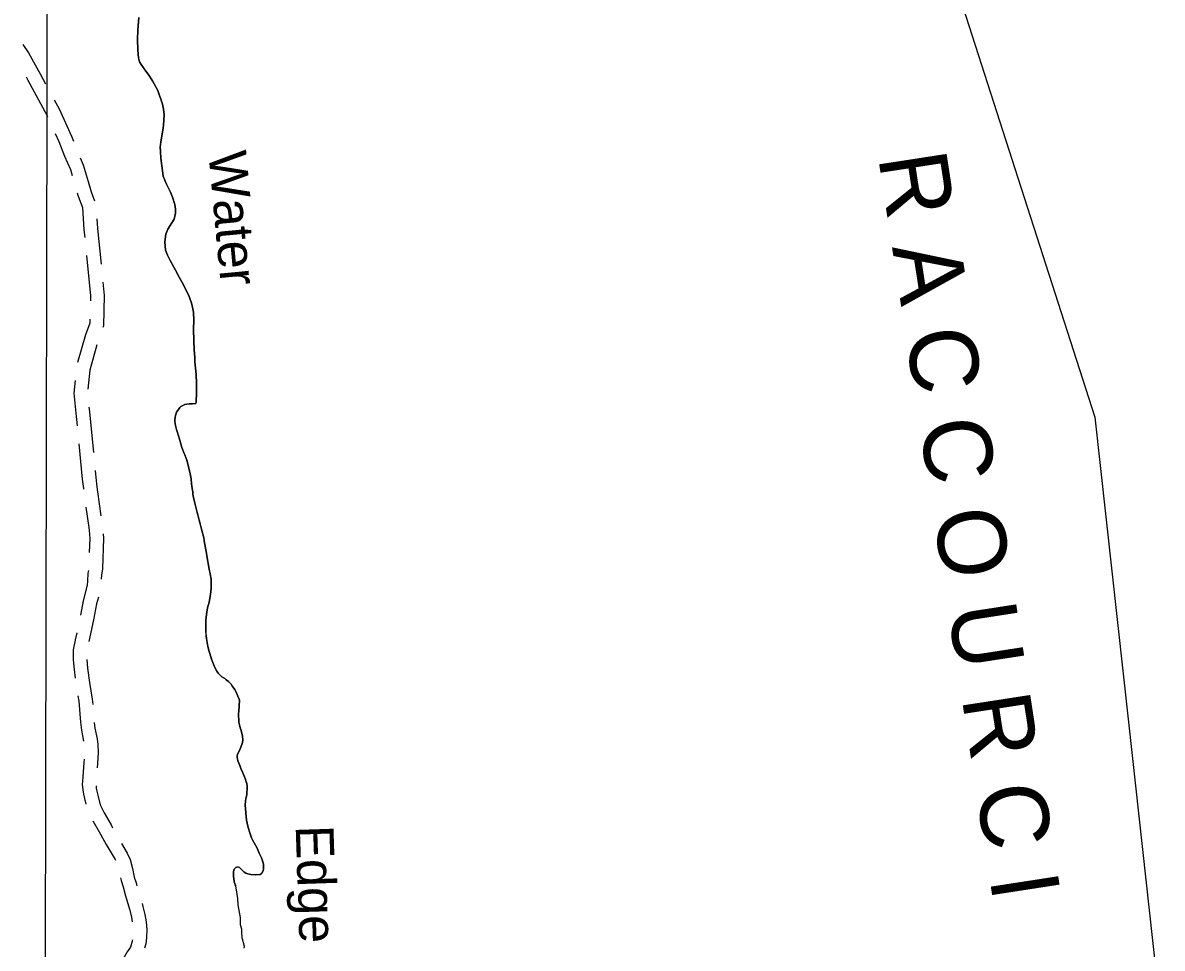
# Model space of a CAD drawing. Extents: x 3192952 to 3230831, y 849296 to 874698.
# Drawn here: x 3207569 to 3210074, y 861699 to 863734 of the extents above; entities that cross this region are included whole.
import ezdxf

# ---------------------------------------------------------------- set-up
doc = ezdxf.new("R2010")
doc.units = 0
for name, color, linetype in [('V-GRID-MAJR', 7, 'Continuous'), ('V-RIVR-IDEN', 7, 'Continuous'), ('V-ROAD-CNTR', 7, 'Continuous'), ('V-SITE-VEGE', 7, 'Continuous'), ('V-TOPO-BNDY', 7, 'Continuous'), ('V-TOPO-SHOR', 7, 'Continuous')]:
    doc.layers.add(name, color=color, linetype=linetype)

msp = doc.modelspace()

# ---------------------------------------------------------------- linework, layer by layer
at = {"layer": 'V-GRID-MAJR'}
msp.add_spline([(3207605.4, 854713.5), (3207617.8, 860773), (3207630.1, 866835.5), (3207642.5, 872898.1), (3207642.5, 872901.1)], degree=3, dxfattribs=at)
at = {"layer": 'V-ROAD-CNTR'}
msp.add_line((3207687.9, 862392.2), (3207684.5, 862376.8), dxfattribs=at)
for points in [[(3207569.5, 863686), (3207582.2, 863667.8), (3207607.3, 863621.8), (3207619.4, 863599.5)], [(3207576.8, 863615.1), (3207580.9, 863607.5), (3207622.3, 863530.8), (3207624.1, 863527)], [(3207638.3, 863564.3), (3207649.2, 863544.2), (3207676.5, 863484.7), (3207680.8, 863473.8)], [(3207640.8, 863490.6), (3207648.9, 863473), (3207661.5, 863440.7), (3207674, 863411.5), (3207678, 863397.9)], [(3207695.8, 863436.7), (3207702.2, 863421.7), (3207713.2, 863385.1), (3207719.5, 863361.9), (3207727.2, 863341.9)], [(3207689.1, 863359.5), (3207690.9, 863352.6), (3207700.5, 863327.7), (3207703.9, 863278.6), (3207705.6, 863261.7)], [(3207732.3, 863302.5), (3207733.8, 863281.1), (3207741.5, 863203)], [(3207709.5, 863221.9), (3207718.2, 863133.2), (3207718, 863122.3)], [(3207745.4, 863163.1), (3207748.3, 863134.3), (3207746.7, 863067.1), (3207745.3, 863063.6)], [(3207717.1, 863082.3), (3207716.9, 863073.1), (3207707, 863047.9), (3207690, 862986.5)], [(3207732, 863025.9), (3207716.6, 862969.9), (3207712.6, 862928.2)], [(3207684.3, 862947), (3207681.7, 862919.5), (3207686.1, 862875.3), (3207688.8, 862847.6)], [(3207714.9, 862888.4), (3207715.9, 862878.3), (3207724.7, 862789)], [(3207692.7, 862807.8), (3207700.3, 862730.7), (3207702.6, 862709.9), (3207702.8, 862708.3)], [(3207728.7, 862749.1), (3207730.2, 862733.8), (3207732.4, 862713.5), (3207733.9, 862702.2), (3207741.1, 862649.9)], [(3207708.2, 862668.7), (3207714.3, 862624.4), (3207715.4, 862617.5), (3207716.8, 862599.9), (3207715.7, 862569.3)], [(3207746, 862610.3), (3207746.8, 862600.6), (3207744.5, 862533.5), (3207744.1, 862528.1), (3207742.2, 862519.9), (3207742, 862510.6)], [(3207713.6, 862529.4), (3207712.3, 862523.7), (3207711.8, 862506.3), (3207711.3, 862497.1), (3207702.4, 862462.8), (3207696.3, 862431.3)], [(3207735.6, 862471.3), (3207731.7, 862456.1), (3207724.9, 862421.4), (3207714.5, 862373.6)], [(3207684.5, 862376.7), (3207680, 862355.5), (3207680.3, 862332.9), (3207682.2, 862311.7), (3207684.5, 862293.2)], [(3207710.3, 862334.1), (3207712, 862314.9), (3207715.9, 862283.4), (3207722.2, 862246.4), (3207723.2, 862235)], [(3207690.6, 862253.7), (3207692.5, 862242.6), (3207696.3, 862196.2), (3207698.3, 862178.5), (3207703, 862154.6)], [(3207726.6, 862195.2), (3207727.9, 862183.1), (3207732.7, 862159.4), (3207734.3, 862147), (3207735.5, 862129.2), (3207733.9, 862105), (3207733.2, 862096)], [(3207704.5, 862114.8), (3207704, 862107.2), (3207700.8, 862065.8), (3207700.1, 862060), (3207701.3, 862047.2), (3207702.8, 862037.6), (3207705.4, 862028.6), (3207708.2, 862015.8)], [(3207730.6, 862056.1), (3207731, 862051), (3207732.2, 862044.1), (3207734.5, 862035.9), (3207739.3, 862014.3), (3207748.1, 861996.9), (3207763.6, 861970.2), (3207766.9, 861964.2)], [(3207723.7, 861979.2), (3207737.5, 861955.4), (3207753.1, 861927), (3207772.4, 861894.3), (3207773.2, 861892.4)], [(3207786.5, 861929.4), (3207799.1, 861908.1), (3207805.3, 861894.1), (3207810.7, 861874.1), (3207814.5, 861855.6), (3207818.7, 861843), (3207820.5, 861836.2)], [(3207784.2, 861854.1), (3207785.5, 861847.8), (3207789.9, 861834.3), (3207795.4, 861814.5), (3207804.7, 861783), (3207808.4, 861767.5), (3207809.9, 861757.5)], [(3207831.7, 861797.7), (3207833.7, 861790.7), (3207837.9, 861773.2), (3207840.3, 861757.3), (3207842.1, 861740), (3207841.2, 861722.7), (3207839.7, 861708.5), (3207836.8, 861699.3)], [(3207810.5, 861717.7), (3207810.2, 861714.7), (3207806, 861701.3), (3207802.9, 861696.3), (3207798.7, 861691.4), (3207793, 861681.3), (3207783.7, 861666.5), (3207776.7, 861656.7), (3207766.4, 861629.7), (3207766.1, 861629.2)]]:
    msp.add_lwpolyline(points, dxfattribs=at)
at = {"layer": 'V-SITE-VEGE'}
for p, q in [((3207822.8, 863726.7), (3207824.7, 863745.5)), ((3207821.8, 863697.9), (3207822.3, 863716.7)), ((3207822.3, 863716.7), (3207822.8, 863726.7)), ((3207822, 863673.8), (3207821.8, 863697.9)), ((3207823.5, 863656.4), (3207822, 863673.8)), ((3207826.3, 863647.7), (3207823.5, 863656.4)), ((3207829.7, 863641.7), (3207826.3, 863647.7)), ((3207839.9, 863627), (3207829.7, 863641.7)), ((3207845.3, 863620.4), (3207839.9, 863627)), ((3207854.8, 863606.4), (3207845.3, 863620.4)), ((3207866.4, 863585.1), (3207854.8, 863606.4)), ((3207876.8, 863555), (3207866.4, 863585.1)), ((3207878.9, 863543.7), (3207876.8, 863555)), ((3207880.4, 863531.6), (3207878.9, 863543.7)), ((3207878, 863502.8), (3207878.6, 863508.8)), ((3207878.6, 863508.8), (3207880.4, 863531.6)), ((3207872.9, 863471.9), (3207874.8, 863484.7)), ((3207874.8, 863484.7), (3207878, 863502.8)), ((3207871.7, 863460.5), (3207872.9, 863471.9)), ((3207872.5, 863450.5), (3207871.7, 863460.5)), ((3207872.6, 863435.7), (3207872.5, 863450.5)), ((3207876.2, 863408.3), (3207872.6, 863435.7)), ((3207878.3, 863396.2), (3207876.2, 863408.3)), ((3207885.2, 863378.9), (3207878.3, 863396.2)), ((3207894.1, 863361.6), (3207885.2, 863378.9)), ((3207898.9, 863350.2), (3207894.1, 863361.6)), ((3207903.7, 863334.2), (3207898.9, 863350.2)), ((3207905.2, 863324.1), (3207903.7, 863334.2)), ((3207902.1, 863302), (3207905.3, 863314.8)), ((3207905.3, 863314.8), (3207905.2, 863324.1)), ((3207888.2, 863279.8), (3207897.4, 863293.9)), ((3207897.4, 863293.9), (3207902.1, 863302)), ((3207881.8, 863252.2), (3207883.6, 863269)), ((3207883.6, 863269), (3207888.2, 863279.8)), ((3207883.3, 863234.1), (3207881.8, 863252.2)), ((3207887.4, 863222.8), (3207883.3, 863234.1)), ((3207893.6, 863210.8), (3207887.4, 863222.8)), ((3207905.2, 863190.1), (3207893.6, 863210.8)), ((3207913.4, 863174.8), (3207905.2, 863190.1)), ((3207922.9, 863157.5), (3207913.4, 863174.8)), ((3207935.2, 863132.1), (3207922.9, 863157.5)), ((3207941.4, 863114.8), (3207935.2, 863132.1)), ((3207944.9, 863097.4), (3207941.4, 863114.8)), ((3207945.1, 863079.3), (3207944.9, 863097.4)), ((3207944.6, 863061.2), (3207945.1, 863079.3)), ((3207945.6, 863033.7), (3207944.6, 863061.2)), ((3207946.4, 863015.7), (3207945.6, 863033.7)), ((3207947.9, 862996.9), (3207946.4, 863015.7)), ((3207948, 862988.2), (3207947.9, 862996.9)), ((3207950.3, 862960.1), (3207948, 862988.2)), ((3207951.2, 862940.7), (3207950.3, 862960.1)), ((3207951.4, 862920.6), (3207951.2, 862940.7)), ((3207950.3, 862899.5), (3207951.4, 862920.6)), ((3207907.4, 862877.7), (3207911.4, 862883.8)), ((3207911.4, 862883.8), (3207914.8, 862887.8)), ((3207914.8, 862887.8), (3207917.2, 862889.8)), ((3207917.2, 862889.8), (3207921.4, 862892.5)), ((3207921.4, 862892.5), (3207926, 862894.3)), ((3207926, 862894.3), (3207930.4, 862895.5)), ((3207930.4, 862895.5), (3207934.9, 862895.8)), ((3207934.9, 862895.8), (3207942.7, 862896)), ((3207942.7, 862896), (3207950.1, 862896.7)), ((3207950.1, 862896.7), (3207950.3, 862899.5)), ((3207903.5, 862860.6), (3207904.1, 862866.2)), ((3207903.5, 862857), (3207903.5, 862860.6)), ((3207904.8, 862848.5), (3207903.5, 862857)), ((3207904.1, 862866.2), (3207904.9, 862870)), ((3207904.9, 862870), (3207907.4, 862877.7)), ((3207907.3, 862839.3), (3207904.8, 862848.5)), ((3207908.9, 862834.9), (3207907.3, 862839.3)), ((3207911, 862828.1), (3207908.9, 862834.9)), ((3207914.4, 862816.2), (3207911, 862828.1)), ((3207919.4, 862800.2), (3207914.4, 862816.2)), ((3207924.3, 862786.6), (3207919.4, 862800.2)), ((3207925.7, 862783.8), (3207924.3, 862786.6)), ((3207929.8, 862771.9), (3207925.7, 862783.8)), ((3207933.7, 862758.5), (3207929.8, 862771.9)), ((3207935.3, 862750.9), (3207933.7, 862758.5)), ((3207936.6, 862745.6), (3207935.3, 862750.9)), ((3207939.3, 862731.4), (3207936.6, 862745.6)), ((3207940.6, 862719.9), (3207939.3, 862731.4)), ((3207941.6, 862709.9), (3207940.6, 862719.9)), ((3207942.9, 862702.5), (3207941.6, 862709.9)), ((3207943.3, 862697.3), (3207942.9, 862702.5)), ((3207944.6, 862690.2), (3207943.3, 862697.3)), ((3207947.4, 862677.8), (3207944.6, 862690.2)), ((3207953, 862656.9), (3207947.4, 862677.8)), ((3207954, 862652.1), (3207953, 862656.9)), ((3207956.9, 862640.3), (3207954, 862652.1)), ((3207959.2, 862632.4), (3207956.9, 862640.3)), ((3207959.8, 862629.4), (3207959.2, 862632.4)), ((3207962.5, 862620.6), (3207959.8, 862629.4)), ((3207967.4, 862601.5), (3207962.5, 862620.6)), ((3207968.5, 862595.7), (3207967.4, 862601.5)), ((3207969.1, 862590.3), (3207968.5, 862595.7)), ((3207973, 862567.8), (3207969.1, 862590.3)), ((3207973.7, 862562), (3207973, 862567.8)), ((3207979.1, 862532.3), (3207973.7, 862562)), ((3207981.2, 862522.4), (3207979.1, 862532.3)), ((3207983.2, 862510.2), (3207981.2, 862522.4)), ((3207983.5, 862502), (3207983.2, 862510.2)), ((3207982, 862477), (3207983.4, 862490.7)), ((3207983.4, 862490.7), (3207983.5, 862502)), ((3207975.4, 862447.2), (3207978.9, 862459.9)), ((3207978.9, 862459.9), (3207982, 862477)), ((3207972.1, 862421.3), (3207974, 862438)), ((3207974, 862438), (3207975.4, 862447.2)), ((3207971.6, 862413.9), (3207972.1, 862421.3)), ((3207971.7, 862398.2), (3207971.6, 862413.9)), ((3207972.3, 862386.9), (3207971.7, 862398.2)), ((3207973.2, 862380.3), (3207972.3, 862386.9)), ((3207976.5, 862362.8), (3207973.2, 862380.3)), ((3207979.2, 862351.6), (3207976.5, 862362.8)), ((3207980.6, 862346.8), (3207979.2, 862351.6)), ((3207984.5, 862334.8), (3207980.6, 862346.8)), ((3207990.2, 862319.9), (3207984.5, 862334.8)), ((3207992.3, 862314.9), (3207990.2, 862319.9)), ((3207995.7, 862308.3), (3207992.3, 862314.9)), ((3207999, 862303.9), (3207995.7, 862308.3)), ((3208003.2, 862299.5), (3207999, 862303.9)), ((3208007.3, 862296.1), (3208003.2, 862299.5)), ((3208013.7, 862291.9), (3208007.3, 862296.1)), ((3208016.6, 862289.3), (3208013.7, 862291.9)), ((3208021.6, 862285.5), (3208016.6, 862289.3)), ((3208027.3, 862279.5), (3208021.6, 862285.5)), ((3208030.7, 862274.9), (3208027.3, 862279.5)), ((3208035.4, 862267.7), (3208030.7, 862274.9)), ((3208037.2, 862264.7), (3208035.4, 862267.7)), ((3208040.9, 862257.1), (3208037.2, 862264.7)), ((3208045.8, 862244.5), (3208040.9, 862257.1)), ((3208044.7, 862219.3), (3208045.8, 862244.5)), ((3208043.6, 862210.2), (3208043.9, 862215.1)), ((3208044, 862201), (3208043.6, 862210.2)), ((3208043.9, 862215.1), (3208044.7, 862219.3)), ((3208044.5, 862196.4), (3208044, 862201)), ((3208045.7, 862190.2), (3208044.5, 862196.4)), ((3208047.4, 862183.5), (3208045.7, 862190.2)), ((3208048.6, 862180.1), (3208047.4, 862183.5)), ((3208050, 862174.9), (3208048.6, 862180.1)), ((3208052.1, 862165.7), (3208050, 862174.9)), ((3208053.1, 862156.6), (3208052.1, 862165.7)), ((3208052.4, 862151.8), (3208053.1, 862156.6)), ((3208041.3, 862125.4), (3208047, 862137.7)), ((3208047, 862137.7), (3208051, 862147.2)), ((3208051, 862147.2), (3208052.4, 862151.8)), ((3208040.9, 862122.4), (3208041.3, 862125.4)), ((3208040.9, 862118.2), (3208040.9, 862122.4)), ((3208041.3, 862115.2), (3208040.9, 862118.2)), ((3208042.2, 862111.3), (3208041.3, 862115.2)), ((3208046.3, 862100.7), (3208042.2, 862111.3)), ((3208048.9, 862094.5), (3208046.3, 862100.7)), ((3208053.2, 862084.9), (3208048.9, 862094.5)), ((3208058.3, 862072.1), (3208053.2, 862084.9)), ((3208060.7, 862065.2), (3208058.3, 862072.1)), ((3208061.6, 862061), (3208060.7, 862065.2)), ((3208062.6, 862055.6), (3208061.6, 862061)), ((3208062.7, 862048.4), (3208062.6, 862055.6)), ((3208059.6, 862028.1), (3208061.7, 862036.1)), ((3208061.7, 862036.1), (3208062.3, 862042.1)), ((3208062.3, 862042.1), (3208062.7, 862048.4)), ((3208058.6, 862013.8), (3208059, 862022.2)), ((3208061.3, 861980.6), (3208058.6, 862013.8)), ((3208059, 862022.2), (3208059.6, 862028.1)), ((3208062.5, 861974.4), (3208061.3, 861980.6)), ((3208064.8, 861964.6), (3208062.5, 861974.4)), ((3208068.5, 861953.1), (3208064.8, 861964.6)), ((3208072.4, 861941.7), (3208068.5, 861953.1)), ((3208074.4, 861937.3), (3208072.4, 861941.7)), ((3208077.8, 861930.9), (3208074.4, 861937.3)), ((3208084.3, 861919.1), (3208077.8, 861930.9)), ((3208089.2, 861908.3), (3208084.3, 861919.1)), ((3208092.3, 861902), (3208089.2, 861908.3)), ((3208094.1, 861897.8), (3208092.3, 861902)), ((3208096.6, 861891), (3208094.1, 861897.8)), ((3208097.8, 861886.8), (3208096.6, 861891)), ((3208098.6, 861883), (3208097.8, 861886.8)), ((3208098.7, 861879), (3208098.6, 861883)), ((3208032.6, 861862.9), (3208032.8, 861867.9)), ((3208032.7, 861856.9), (3208032.6, 861862.9)), ((3208033.3, 861852), (3208032.7, 861856.9)), ((3208032.8, 861867.9), (3208034.4, 861872.8)), ((3208034.4, 861872.8), (3208037.4, 861876.6)), ((3208037.4, 861876.6), (3208042, 861878.2)), ((3208042, 861878.2), (3208045.6, 861876.6)), ((3208045.6, 861876.6), (3208049.1, 861873.8)), ((3208049.1, 861873.8), (3208055.7, 861866.9)), ((3208055.7, 861866.9), (3208060, 861864.5)), ((3208060, 861864.5), (3208063.8, 861862.9)), ((3208063.8, 861862.9), (3208066.8, 861861.9)), ((3208066.8, 861861.9), (3208071, 861860.9)), ((3208071, 861860.9), (3208081.5, 861860.4)), ((3208081.5, 861860.4), (3208091.3, 861861)), ((3208091.3, 861861), (3208094.7, 861864.3)), ((3208094.7, 861864.3), (3208097.5, 861869.5)), ((3208097.5, 861869.5), (3208098.5, 861873.7)), ((3208098.5, 861873.7), (3208098.7, 861879)), ((3208034.4, 861844.8), (3208033.3, 861852)), ((3208035.4, 861841.4), (3208034.4, 861844.8)), ((3208036.6, 861838.6), (3208035.4, 861841.4)), ((3208038.1, 861836.6), (3208036.6, 861838.6)), ((3208041.9, 861808.8), (3208038.1, 861836.6)), ((3208043.2, 861794.2), (3208041.9, 861808.8)), ((3208045.7, 861778.4), (3208043.2, 861794.2)), ((3208048.3, 861766.5), (3208045.7, 861778.4)), ((3208048.2, 861750.6), (3208048.3, 861766.5)), ((3208050.8, 861741.3), (3208048.2, 861750.6)), ((3208050.7, 861730.8), (3208050.8, 861741.3)), ((3208052, 861726.8), (3208050.7, 861730.8)), ((3208052, 861721.5), (3208052, 861726.8)), ((3208053.3, 861717.5), (3208052, 861721.5)), ((3208054.5, 861710.9), (3208053.3, 861717.5)), ((3208057.1, 861703), (3208054.5, 861710.9)), ((3208055.8, 861699), (3208057.1, 861703))]:
    msp.add_line(p, q, dxfattribs=at)
at = {"layer": 'V-TOPO-BNDY'}
for p, q in [((3209621.7, 863811.9), (3209926, 862866.7)), ((3209926, 862866.7), (3209999.7, 862195.8)), ((3209999.7, 862195.8), (3210074.1, 861524.8))]:
    msp.add_line(p, q, dxfattribs=at)
at = {"layer": 'V-TOPO-SHOR'}
for points in [[(3207824.7, 863745.5), (3207822.8, 863726.7), (3207822.3, 863716.7), (3207821.8, 863697.9), (3207822, 863673.8), (3207823.5, 863656.4), (3207826.3, 863647.7), (3207829.7, 863641.7), (3207839.9, 863627), (3207845.3, 863620.4), (3207854.8, 863606.4), (3207866.4, 863585.1), (3207876.8, 863555), (3207878.9, 863543.7), (3207880.4, 863531.6), (3207878.6, 863508.8), (3207878, 863502.8), (3207874.8, 863484.7), (3207872.9, 863471.9), (3207871.7, 863460.5), (3207872.5, 863450.5), (3207872.6, 863435.7), (3207876.2, 863408.3), (3207878.3, 863396.2), (3207885.2, 863378.9), (3207894.1, 863361.6), (3207898.9, 863350.2), (3207903.7, 863334.2), (3207905.2, 863324.1), (3207905.3, 863314.8), (3207902.1, 863302), (3207897.4, 863293.9), (3207888.2, 863279.8), (3207883.6, 863269), (3207881.8, 863252.2), (3207883.3, 863234.1), (3207887.4, 863222.8), (3207893.6, 863210.8), (3207905.2, 863190.1), (3207913.4, 863174.8), (3207922.9, 863157.5), (3207935.2, 863132.1)], [(3207935.2, 863132.1), (3207941.4, 863114.8), (3207944.9, 863097.4), (3207945.1, 863079.3), (3207944.6, 863061.2), (3207945.6, 863033.7), (3207946.4, 863015.7), (3207947.9, 862996.9), (3207948, 862988.2), (3207950.3, 862960.1), (3207951.2, 862940.7), (3207951.4, 862920.6), (3207950.3, 862899.5)], [(3207950.3, 862899.5), (3207950.1, 862896.7), (3207942.7, 862896), (3207934.9, 862895.8), (3207930.4, 862895.5), (3207926, 862894.3), (3207921.4, 862892.5), (3207917.2, 862889.8), (3207914.8, 862887.8), (3207911.4, 862883.8), (3207907.4, 862877.7), (3207904.9, 862870), (3207904.1, 862866.2), (3207903.5, 862860.6), (3207903.5, 862857), (3207904.8, 862848.5), (3207907.3, 862839.3), (3207908.9, 862834.9), (3207911, 862828.1), (3207914.4, 862816.2), (3207919.4, 862800.2), (3207924.3, 862786.6), (3207925.7, 862783.8), (3207929.8, 862771.9), (3207933.7, 862758.5), (3207935.3, 862750.9), (3207936.6, 862745.6), (3207939.3, 862731.4), (3207940.6, 862719.9), (3207941.6, 862709.9), (3207942.9, 862702.5), (3207943.3, 862697.3), (3207944.6, 862690.2), (3207947.4, 862677.8), (3207953, 862656.9), (3207954, 862652.1), (3207956.9, 862640.3), (3207959.2, 862632.4), (3207959.8, 862629.4), (3207962.5, 862620.6), (3207967.4, 862601.5), (3207968.5, 862595.7), (3207969.1, 862590.3), (3207973, 862567.8), (3207973.7, 862562), (3207979.1, 862532.3), (3207981.2, 862522.4), (3207983.2, 862510.2), (3207983.5, 862502), (3207983.4, 862490.7), (3207982, 862477), (3207978.9, 862459.9), (3207975.4, 862447.2), (3207974, 862438), (3207972.1, 862421.3), (3207971.6, 862413.9), (3207971.6, 862409.4), (3207971.7, 862398.2), (3207972.1, 862390.5), (3207972.3, 862386.9), (3207973.2, 862380.3), (3207976.5, 862362.8), (3207979.2, 862351.6), (3207980.6, 862346.8), (3207984.5, 862334.8), (3207990.2, 862319.9), (3207992.3, 862314.9), (3207995.7, 862308.3), (3207999, 862303.9), (3208003.2, 862299.5), (3208007.3, 862296.1), (3208013.7, 862291.9), (3208016.6, 862289.3), (3208021.6, 862285.5), (3208027.3, 862279.5), (3208030.7, 862274.9), (3208035.4, 862267.7), (3208037.2, 862264.7), (3208040.9, 862257.1), (3208045.8, 862244.5), (3208044.7, 862219.3), (3208043.9, 862215.1), (3208043.6, 862210.2), (3208044, 862201), (3208044.5, 862196.4), (3208045.7, 862190.2), (3208047.4, 862183.5), (3208048.6, 862180.1), (3208050, 862174.9), (3208052.1, 862165.7), (3208053.1, 862156.6), (3208052.4, 862151.8), (3208051, 862147.2), (3208047, 862137.7), (3208041.3, 862125.4), (3208040.9, 862122.4), (3208040.9, 862118.2), (3208041.3, 862115.2), (3208042.2, 862111.3), (3208046.3, 862100.7), (3208048.9, 862094.5)], [(3208048.9, 862094.5), (3208053.2, 862084.9), (3208058.3, 862072.1), (3208060.7, 862065.2), (3208061.6, 862061), (3208062.6, 862055.6), (3208062.7, 862048.4), (3208062.3, 862042.1), (3208061.7, 862036.1), (3208059.6, 862028.1), (3208059, 862022.2), (3208058.6, 862013.8), (3208061.3, 861980.6), (3208062.5, 861974.4), (3208064.8, 861964.6), (3208068.5, 861953.1), (3208072.4, 861941.7), (3208074.4, 861937.3), (3208077.8, 861930.9), (3208084.3, 861919.1), (3208089.2, 861908.3), (3208092.3, 861902), (3208094.1, 861897.8), (3208096.6, 861891), (3208097.8, 861886.8), (3208098.6, 861883), (3208098.7, 861879), (3208098.5, 861873.7), (3208097.5, 861869.5), (3208094.7, 861864.3), (3208091.3, 861861), (3208081.5, 861860.4), (3208071, 861860.9), (3208066.8, 861861.9), (3208063.8, 861862.9), (3208060, 861864.5), (3208055.7, 861866.9), (3208049.1, 861873.8), (3208045.6, 861876.6), (3208042, 861878.2), (3208037.4, 861876.6), (3208034.4, 861872.8), (3208032.8, 861867.9), (3208032.6, 861862.9), (3208032.7, 861856.9), (3208033.3, 861852), (3208034.4, 861844.8), (3208035.4, 861841.4), (3208036.6, 861838.6), (3208038.1, 861836.6)], [(3208055.8, 861699), (3208057.1, 861703), (3208054.5, 861710.9), (3208053.3, 861717.5), (3208052, 861721.5), (3208052, 861726.8), (3208050.7, 861730.8), (3208050.8, 861741.3), (3208048.2, 861750.6), (3208048.3, 861766.5), (3208045.7, 861778.4), (3208043.2, 861794.2), (3208041.9, 861808.8), (3208038.1, 861836.6)]]:
    msp.add_lwpolyline(points, dxfattribs=at)

# ---------------------------------------------------------------- texts
at = {"layer": 'V-RIVR-IDEN'}
for s, height, rotation, p in [('Water', 83, 275.3347, (3207977.4, 863447.9)), ('R A C C O U R C I', 150, 278.7837, (3209449.4, 863438.8)), ('Edge', 83, 271.8889, (3208169.2, 861968.3))]:
    msp.add_text(s, height=height, rotation=rotation, dxfattribs=at).set_placement(p)

doc.saveas('drawing.dxf')
